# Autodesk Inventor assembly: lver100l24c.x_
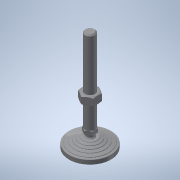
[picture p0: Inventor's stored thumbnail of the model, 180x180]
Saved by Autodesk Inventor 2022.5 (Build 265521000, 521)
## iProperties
Part Number: lver100l24c.x_
Material: 一般
Document SubType Name: Assembly
Designer: ImaoCorp
Sending System: SOLIDWORKS 2017-2017317
MC: AMD64
MC_MODEL: Intel64 Family 6 Model 60 Stepping 3, GenuineIntel
OS: Windows_NT
FRU: Parasolid Version 29.0, build 201,  4-17-2017
FORMAT: text
GUISE: transmit
KEY: lver100l24c
FILE: lver100l24c.x_t
DATE: Mon Jul 01 18:23:24 2019
Author: ImaoCorp
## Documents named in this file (3)
- X:\14_SW2022-Inv2022\00_全2023-1023新製品(TCC)まで\l\lver100l24c\LVER100L24C.iam
- X:\14_SW2022-Inv2022\00_全2023-1023新製品(TCC)まで\l\lver100l24c\lver100l24c_01.ipt
- X:\14_SW2022-Inv2022\00_全2023-1023新製品(TCC)まで\l\lver100l24c\lver100l24c_02.ipt
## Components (2 placed, 2 different names)
1. lver100l24c_01
2. lver100l24c_02
